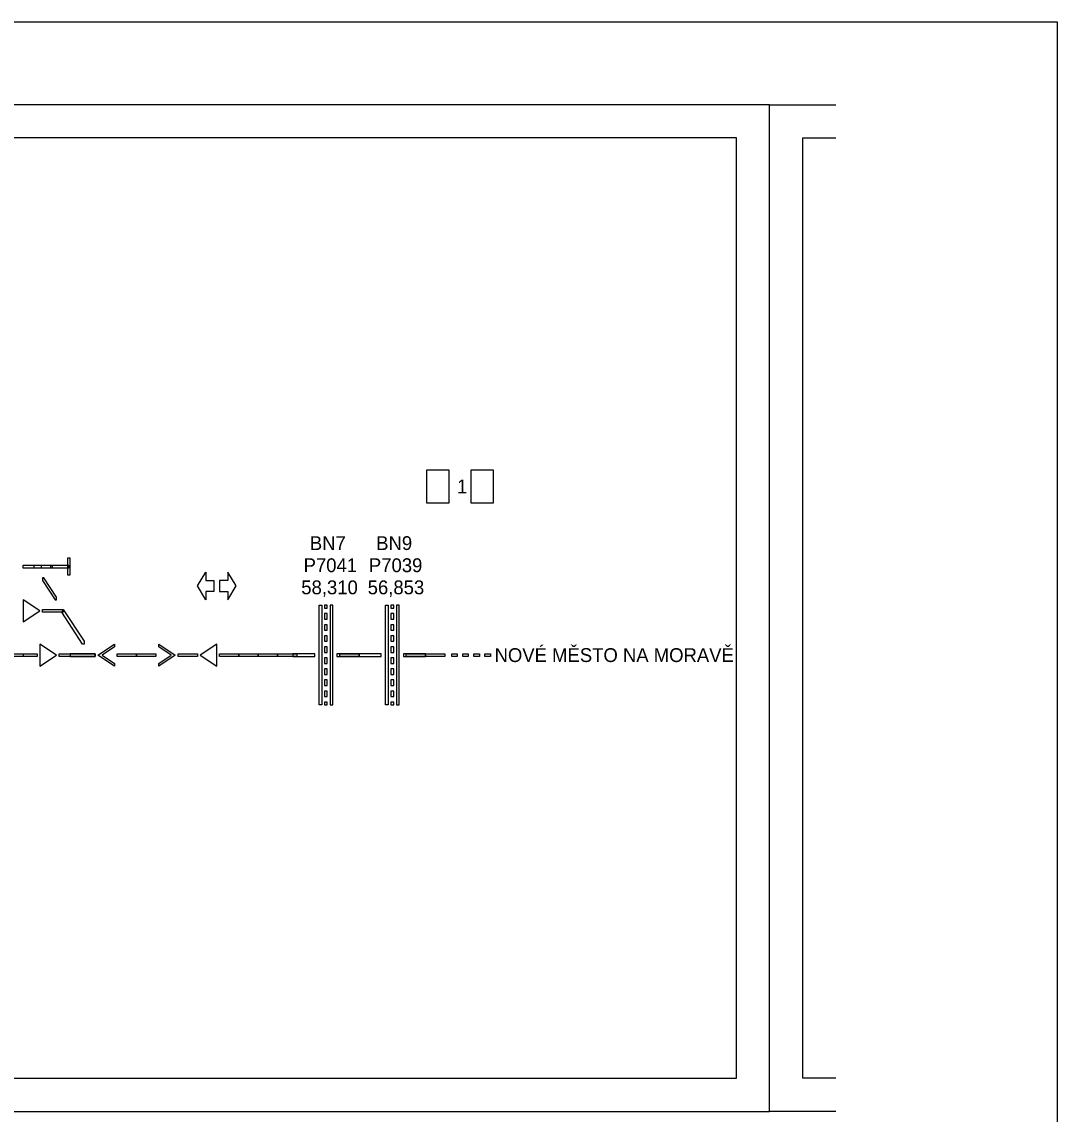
# Model space of a CAD drawing. Extents: x -1424 to 5155, y -2900 to 2050.
# Drawn here: x 2972.8 to 3160, y -2250.5 to -2053 of the extents above; entities that cross this region are included whole.
import ezdxf

# ---------------------------------------------------------------- set-up
doc = ezdxf.new("R2010")
doc.units = 0
doc.layers.add('Vrstva 1', color=7, linetype='Continuous')
doc.layers.add('Vrstva 2', color=7, linetype='Continuous')

msp = doc.modelspace()

# ---------------------------------------------------------------- linework, layer by layer
for points in [[(2796, -2250), (3108, -2250), (3108, -2068), (2796, -2068)], [(2802, -2244), (3102, -2244), (3102, -2074), (2802, -2074)]]:
    msp.add_lwpolyline(points, close=True)
for points in [[(3120, -2250), (3108, -2250), (3108, -2068), (3120, -2068)], [(3120, -2244), (3114, -2244), (3114, -2074), (3120, -2074)]]:
    msp.add_lwpolyline(points)
at = {"layer": 'Vrstva 1'}
for points in [[(3160, -2350), (2740, -2350), (2740, -2053), (3160, -2053)], [(2981, -2153), (2981.5, -2153), (2981.5, -2150), (2981, -2150)], [(2976.25, -2151.75), (2973, -2151.75), (2973, -2151.25), (2976.25, -2151.25)], [(2978.25, -2151.75), (2975, -2151.75), (2975, -2151.25), (2978.25, -2151.25)], [(2981.25, -2151.75), (2978, -2151.75), (2978, -2151.25), (2981.25, -2151.25)], [(3007.5, -2154), (3007.5, -2156), (3006, -2156), (3006, -2157.5), (3004.5, -2155), (3006, -2152.5), (3006, -2154)], [(3008.5, -2154), (3008.5, -2156), (3010, -2156), (3010, -2157.5), (3011.5, -2155), (3010, -2152.5), (3010, -2154)], [(2979, -2157.5), (2979, -2157), (2976.75, -2153.5), (2976.5, -2153.5), (2976.5, -2154), (2978.75, -2157.5)], [(2973, -2157.5), (2973, -2161.5), (2976, -2159.5)], [(3027, -2176.5), (3026.5, -2176.5), (3026.5, -2158.5), (3027, -2158.5)], [(3028, -2158.5), (3027.5, -2158.5), (3027.5, -2159), (3028, -2159)], [(3029, -2158.5), (3028.5, -2158.5), (3028.5, -2176.5), (3029, -2176.5)], [(3039, -2176.5), (3038.5, -2176.5), (3038.5, -2158.5), (3039, -2158.5)], [(3040, -2158.5), (3039.5, -2158.5), (3039.5, -2159), (3040, -2159)], [(3041, -2158.5), (3040.5, -2158.5), (3040.5, -2176.5), (3041, -2176.5)], [(2980.25, -2159.75), (2976.5, -2159.75), (2976.5, -2159.25), (2980.25, -2159.25)], [(2984, -2165), (2984, -2165.5), (2983.75, -2165.5), (2980, -2159.75), (2980.25, -2159.25)], [(3028, -2160), (3027.5, -2160), (3027.5, -2161), (3028, -2161)], [(3040, -2160), (3039.5, -2160), (3039.5, -2161), (3040, -2161)], [(3028, -2162), (3027.5, -2162), (3027.5, -2163), (3028, -2163)], [(3040, -2162), (3039.5, -2162), (3039.5, -2163), (3040, -2163)], [(3028, -2164), (3027.5, -2164), (3027.5, -2165), (3028, -2165)], [(3040, -2164), (3039.5, -2164), (3039.5, -2165), (3040, -2165)], [(2976, -2165.5), (2976, -2169.5), (2979, -2167.5)], [(2989.5, -2169.5), (2986.5, -2167.5), (2989.5, -2165.5), (2989.5, -2166), (2987.25, -2167.5), (2989.5, -2169)], [(2989.5, -2169.5), (2986.5, -2167.5), (2989.5, -2165.5), (2989.5, -2166), (2987.25, -2167.5), (2989.5, -2169)], [(2997.5, -2165.5), (3000.5, -2167.5), (2997.5, -2169.5), (2997.5, -2169), (2999.75, -2167.5), (2997.5, -2166)], [(3008, -2169.5), (3008, -2165.5), (3005, -2167.5)], [(3008, -2169.5), (3008, -2165.5), (3005, -2167.5)], [(3008, -2169.5), (3008, -2165.5), (3005, -2167.5)], [(3008, -2169.5), (3008, -2165.5), (3005, -2167.5)], [(3028, -2166), (3027.5, -2166), (3027.5, -2167), (3028, -2167)], [(3040, -2166), (3039.5, -2166), (3039.5, -2167), (3040, -2167)], [(2973, -2167.75), (2966, -2167.75), (2966, -2167.25), (2973, -2167.25)], [(2975.5, -2167.75), (2968.5, -2167.75), (2968.5, -2167.25), (2975.5, -2167.25)], [(2986, -2167.75), (2979.5, -2167.75), (2979.5, -2167.25), (2986, -2167.25)], [(2981.5, -2167.75), (2986, -2167.75), (2986, -2167.25), (2981.5, -2167.25)], [(2993.5, -2167.75), (2990, -2167.75), (2990, -2167.25), (2993.5, -2167.25)], [(2993.5, -2167.75), (2990, -2167.75), (2990, -2167.25), (2993.5, -2167.25)], [(2997, -2167.75), (2993.5, -2167.75), (2993.5, -2167.25), (2997, -2167.25)], [(3004.5, -2167.75), (3001, -2167.75), (3001, -2167.25), (3004.5, -2167.25)], [(3012, -2167.75), (3008.5, -2167.75), (3008.5, -2167.25), (3012, -2167.25)], [(3015.5, -2167.75), (3012, -2167.75), (3012, -2167.25), (3015.5, -2167.25)], [(3019, -2167.75), (3015.5, -2167.75), (3015.5, -2167.25), (3019, -2167.25)], [(3022.5, -2167.75), (3019, -2167.75), (3019, -2167.25), (3022.5, -2167.25)], [(3025.75, -2167.25), (3021.75, -2167.25), (3021.75, -2167.75), (3025.75, -2167.75)], [(3028, -2168), (3027.5, -2168), (3027.5, -2169), (3028, -2169)], [(3033.75, -2167.25), (3029.75, -2167.25), (3029.75, -2167.75), (3033.75, -2167.75)], [(3033.75, -2167.75), (3030.25, -2167.75), (3030.25, -2167.25), (3033.75, -2167.25)], [(3037.75, -2167.25), (3033.75, -2167.25), (3033.75, -2167.75), (3037.75, -2167.75)], [(3040, -2168), (3039.5, -2168), (3039.5, -2169), (3040, -2169)], [(3045.75, -2167.25), (3041.75, -2167.25), (3041.75, -2167.75), (3045.75, -2167.75)], [(3045.75, -2167.75), (3042.25, -2167.75), (3042.25, -2167.25), (3045.75, -2167.25)], [(3049.25, -2167.75), (3045.75, -2167.75), (3045.75, -2167.25), (3049.25, -2167.25)], [(3051.5, -2167.75), (3050.5, -2167.75), (3050.5, -2167.25), (3051.5, -2167.25)], [(3051.5, -2167.75), (3050.5, -2167.75), (3050.5, -2167.25), (3051.5, -2167.25)], [(3053.5, -2167.75), (3052.5, -2167.75), (3052.5, -2167.25), (3053.5, -2167.25)], [(3053.5, -2167.75), (3052.5, -2167.75), (3052.5, -2167.25), (3053.5, -2167.25)], [(3055.5, -2167.75), (3054.5, -2167.75), (3054.5, -2167.25), (3055.5, -2167.25)], [(3055.5, -2167.75), (3054.5, -2167.75), (3054.5, -2167.25), (3055.5, -2167.25)], [(3057.5, -2167.75), (3056.5, -2167.75), (3056.5, -2167.25), (3057.5, -2167.25)], [(3028, -2170), (3027.5, -2170), (3027.5, -2171), (3028, -2171)], [(3040, -2170), (3039.5, -2170), (3039.5, -2171), (3040, -2171)], [(3028, -2172), (3027.5, -2172), (3027.5, -2173), (3028, -2173)], [(3040, -2172), (3039.5, -2172), (3039.5, -2173), (3040, -2173)], [(3028, -2174), (3027.5, -2174), (3027.5, -2175), (3028, -2175)], [(3040, -2174), (3039.5, -2174), (3039.5, -2175), (3040, -2175)], [(3028, -2176), (3027.5, -2176), (3027.5, -2176.5), (3028, -2176.5)], [(3040, -2176), (3039.5, -2176), (3039.5, -2176.5), (3040, -2176.5)]]:
    msp.add_lwpolyline(points, close=True, dxfattribs=at)
at = {"layer": 'Vrstva 2'}
for points in [[(3046, -2134), (3050, -2134), (3050, -2140), (3046, -2140)], [(3054, -2134), (3058, -2134), (3058, -2140), (3054, -2140)]]:
    msp.add_lwpolyline(points, close=True, dxfattribs=at)

# ---------------------------------------------------------------- texts
at = {"layer": 'Vrstva 1'}
for s, p in [('1', (3051.47, -2138.25)), ('BN7', (3024.84, -2148.5)), ('BN9', (3036.84, -2148.5)), ('P7041', (3023.71, -2152.5)), ('P7039', (3035.52, -2152.5)), ('58,310', (3023.29, -2156.5)), ('56,853', (3035.3, -2156.5))]:
    msp.add_text(s, height=2.5, dxfattribs=at).set_placement(p)
msp.add_text('NOVÉ MĚSTO NA MORAVĚ', height=2.5, rotation=360, dxfattribs=at).set_placement((3058.25, -2168.75))

doc.saveas('drawing.dxf')
